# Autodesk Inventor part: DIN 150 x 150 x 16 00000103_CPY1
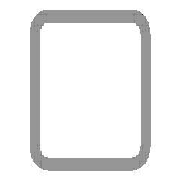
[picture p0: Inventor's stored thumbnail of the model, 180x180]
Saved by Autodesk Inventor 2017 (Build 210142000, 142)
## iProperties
Created: 2017-11
Part Number: DIN 150 x 150 x 16 00000103_CPY1
Material: Steel, Mild
Description: Cold formed welded structural hollow sections of non-alloy and fine grain structural steel
Document SubType Name: Modeling
Standard: DIN
Designer: iusti
Standard Revision: 2006-07
Standards Organization: DIN
Language: en-US
Size Designation: 150 x 150 x 16
Categories: <MemberInstance><Categories><Category DisplayName="Structural Shapes" InternalName="089c4875-fa83-4c05-b084-43b9cc11f5ed" Mnemonic="GRDR"><CategoryParameter Dis
Stock Number: 150 x 150 x 16
Mass: 90369.3 g
Surface Area: 14539.6 cm^2
Volume: 11512 cm^3
Density: 7.85 g/cm^3
Appearance: Semi-Polished
IsCustomPart: 1
G_W: 150.000 mm
G_H: 150.000 mm
G_L: 1539.608 mm
+B4BE7288-8744-4333-8402-F61C489DE7FB+CUTDETAIL2: Cut
_CCFamilyMember: 76
_CCFamilyDisplayName: DIN EN 10219-2 (Square Hollow Section - Cold Formed) - Cold formed welded structural hollow sections of non-alloy and fine grain structural steel
_FrameMemberDoc: Frame Member File
_Version: 15.0.0
_GetPNFromCC: 1
Author: iusti
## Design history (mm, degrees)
node "Start plane"
node "End plane"
sketch "Sketch"
  geometry: L1 (-75, -27)-(-75, 27); L2 (-27, 75)-(27, 75); L3 (75, 27)-(75, -27); L4 (27, -75)-(-27, -75); L5 (-27, 59)-(27, 59); L6 (59, 27)-(59, -27); L7 (27, -59)-(-27, -59); L8 (-59, -27)-(-59, 27); L9 (0, 118.918)-(0, -118.918) reference; L10 (-118.918, 0)-(118.918, 0) reference; A1 r 48 centre (-27, -27) between (-75, -27) and (-27, -75); A2 r 48 centre (-27, 27) between (-27, 75) and (-75, 27); A3 r 48 centre (27, 27) between (75, 27) and (27, 75); A4 r 48 centre (27, -27) between (27, -75) and (75, -27); A5 r 32 centre (-27, 27) between (-27, 59) and (-59, 27); A6 r 32 centre (27, 27) between (59, 27) and (27, 59); A7 r 32 centre (27, -27) between (27, -59) and (59, -27); A8 r 32 centre (-27, -27) between (-59, -27) and (-27, -59)
  constraints: 16 end point, 16 point on circle, 8 centre point, 8 tangent, 4 parallel, 3 equal radius, 2 perpendicular, 7 other
  dimensions: "d7" = 48 radius of A1 (= G_IR); "d10" = 150 distance between parallel lines of L2 L4 (= G_H); "d11" = 150 distance between parallel lines of L1 L3 (= G_W); "d12" = 16 distance between parallel lines of L3 L6 (= G_T); "d15" = 75 distance between parallel lines of L2 L10 (= 0.5 x d10); "d16" = 75 distance between parallel lines of L9 L3 (= 0.5 x d11)
extrude "Body" new body sketch "Sketch" stored distance "d3" = 1539.60835 (= G_L); taper "d4" = 0 deg
node "Driven Length"
  sketch "Sketch3"
    geometry: L1 (0, 0)-(10, 0) reference
    constraints: 2 end point, 1 horizontal
  workplane "Work Plane3"
  sketch "Sketch4"
    geometry: L1 (-2, 75)-(12, 75) reference; L2 (-2, 1614.608)-(12, 1614.608) reference
    dimensions: "d18" = 1539.60835 distance between parallel lines of L1 L2 (derived)
workplane "Work Plane5"
split "Split2"
body "Solid1"
other parameters: "G_W" = 150 [user parameter; used in 1 equation term], "G_H" = 150 [user parameter; used in 1 equation term], "G_T" = 16 [user parameter; used in 1 equation term], "G_IR" = 48 [user parameter; used in 1 equation term], "G_L" = 1539.60835 (= d18) [user parameter; used in 1 equation term], "G_OFFSET_START" = -75 [user parameter; used in 1 equation term], "G_OFFSET_END" = 0 [user parameter; used in 1 equation term], "d13" = 75 (= -G_OFFSET_START), "d14" = 1614.60835 (= G_OFFSET_END + B_L), "B_L" = 1614.60835 [user parameter; used in 1 equation term], "d17" = 90 deg
